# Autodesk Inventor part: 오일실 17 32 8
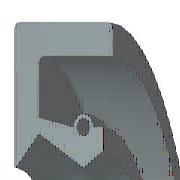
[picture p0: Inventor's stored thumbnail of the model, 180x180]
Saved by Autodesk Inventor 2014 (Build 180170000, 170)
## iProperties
IsCustomPart: 1
Created: 2012-02
Part Number: 오일실 17 32 8
Material: 고무
Description: 오일-실
Document SubType Name: Modeling
Standard: KS B 2804
Designer: mduedu
Standards Organization: KS
Language: ko-KR
Size Designation: D - 17 32 8
Categories: <MemberInstance><Categories><Category DisplayName="샤프트 부품" InternalName="7f7aeb1f-a693-4053-b835-cee3144e0d98" Mnemonic="SHFT"><Category DisplayName="실링" Intern
Density: 0.93 g/cm^3
Appearance: 고무 - 검은색 - 버전 1.1
Mass: 2.28027 g
Surface Area: 32.1224 cm^2
Volume: 2.45191 cm^3
Author: mduedu
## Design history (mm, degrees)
revolve "본체" stored, may be unused: angle "d17" = 90 deg
revolve "스프링1" stored, may be unused: angle "d18" = 90 deg
body "Solid1"
sketch "스케치1"
  geometry: L1 (0, 16)-(8, 16); L2 (8, 14.25)-(1.75, 14.25); L3 (1.75, 10.25)-(4.9, 8.5); L4 (4.9, 8.5)-(0, 8.5); L5 (0, 0)-(9.586, 0) reference; L6 (4.9, 8.5)-(6.3, 9.375); L7 (0, 18)-(0, -3) reference; L8 (-1.941, 0)-(11.507, 0) reference; L9 (4.2, 10.6)-(1.75, 11.21); L10 (1.75, 11.21)-(1.75, 14.25); L11 (0, 16)-(0, 8.588); L12 (4.9, 8.5)-(0, 8.5); L13 (1.75, 10.25)-(0.152, 8.528); L14 (8, 16)-(8, 14.25); L15 (5.6, 10.6)-(6.3, 10.6); L16 (6.3, 10.6)-(6.3, 9.375); C1 r 0.455 at (4.9, 10.6); A1 r 0.7 centre (4.9, 10.6) between (5.6, 10.6) and (4.2, 10.6); A2 r 0.088 centre (0.088, 8.588) between (0, 8.588) and (0.152, 8.528); 1 further point
  constraints: 28 end point, 5 horizontal alignment, 5 point on line, 4 point on circle, 4 vertical alignment, 3 centre point, 3 tangent, 2 collinear, 2 horizontal, 2 perpendicular, 1 coincident, 1 parallel
  dimensions: "d0" = 32 diameter of L1 L5 (= SD2); "d1" = 1.75 distance of L1.end L2.start (= SD); "d2" = 0.91 diameter of C1 (= SPDI); "d3" = 1.4 diameter of A1 (= SPDA); "d4" = 17 diameter of L3.end L5 (= NND); "d5" = 20.5 diameter of L3.start L5 (= TKDM); "d7" = 22.42 diameter of L9.end L5 (= TKDM + 0.24 x SWDT); "d8" = 1.75 distance between parallel lines of L11 L10 (= SD); "d9" = 4.9 distance from line of L11 C1.centre (= SPDST); "d10" = 21.2 diameter of C1.centre L5 (= HLDM); "d11" = 0.0875 radius of A2 (= 0.25 x LAB); "d12" = 6.3 distance between parallel lines of L11 L16 (= SDI); "d13" = 18.75 diameter of L6.end L5 (= ABDM); "d14" = 8 distance from line of L11 L1.end (= SWDT)
fillet "모깎기1" dims "d6" = 0.3 (= RR)
other parameters: "SD2" = 32 [user parameter; used in 1 equation term], "SWDT" = 8 [user parameter; used in 2 equation terms], "RR" = 0.3 [user parameter; used in 1 equation term], "SD" = 1.75 [user parameter; used in 2 equation terms], "NND" = 17 [user parameter; used in 1 equation term], "SPDA" = 1.4 [user parameter; used in 1 equation term], "SPDI" = 0.91 [user parameter; used in 1 equation term], "TKDM" = 20.5 [user parameter; used in 2 equation terms], "HLDM" = 21.2 [user parameter; used in 1 equation term], "ABDM" = 18.75 [user parameter; used in 1 equation term], "SDI" = 6.3 [user parameter; used in 1 equation term], "SPDST" = 4.9 [user parameter; used in 1 equation term], "LAB" = 0.35 [user parameter; used in 1 equation term], "d15" = 0, "d16" = 0, "d19" = 0
